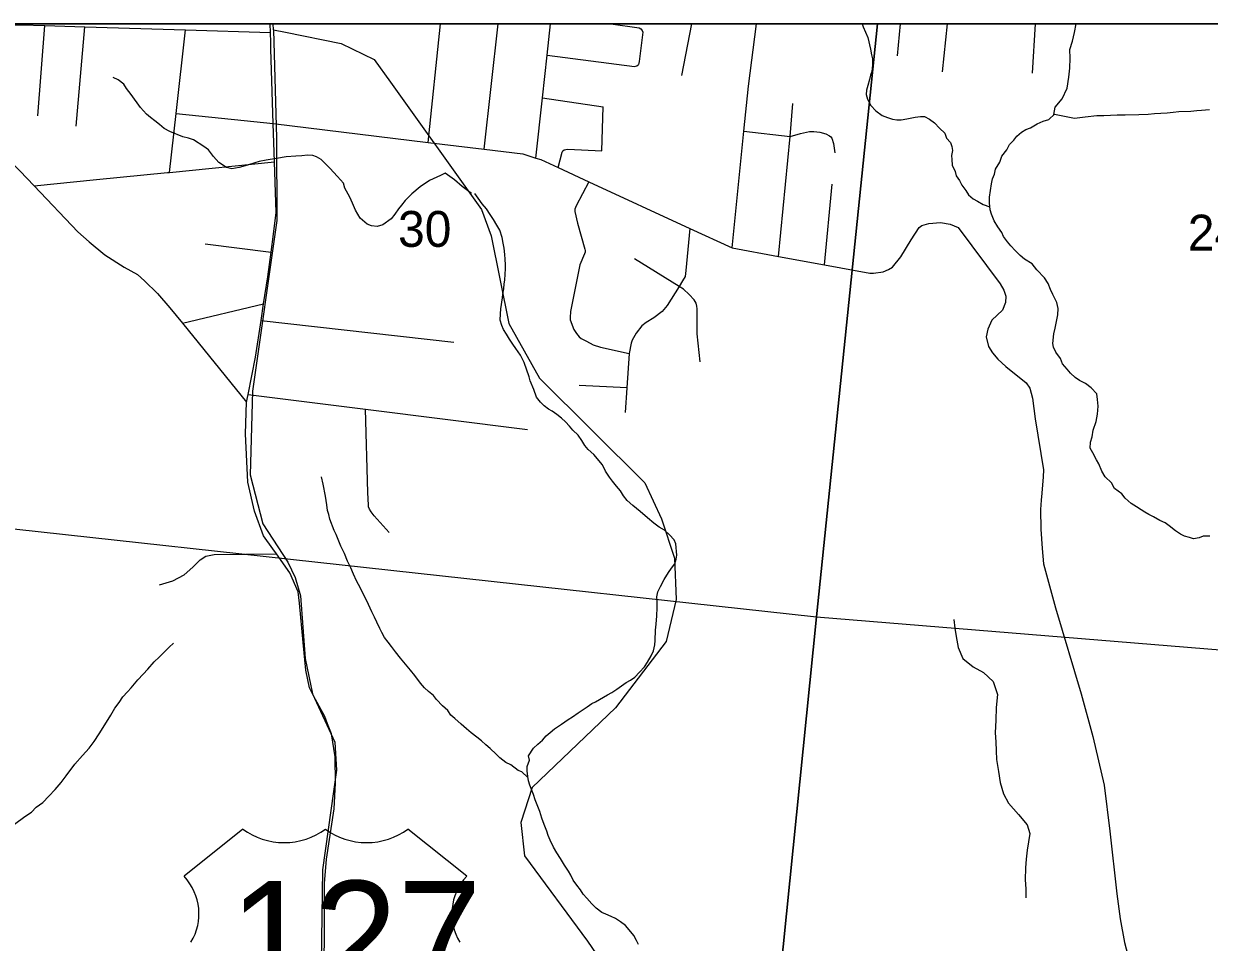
# Model space of a CAD drawing. Extents: x -8.2 to 38.5, y -0.1 to 21.9.
# Drawn here: x 5.115 to 6.498, y 19.692 to 20.764 of the extents above; entities that cross this region are included whole.
import ezdxf

# ---------------------------------------------------------------- set-up
doc = ezdxf.new("R2010")
doc.units = 0
for name, color, linetype in [('Default', 7, 'Continuous'), ('GM_X_Adjacent_County_Text', 7, 'Continuous'), ('GM_X_Airport_Location_Class_3', 7, 'Continuous'), ('GM_X_County_Road_Text', 7, 'Continuous'), ('GM_X_Minor_River', 7, 'Continuous'), ('GM_X_Section', 7, 'Continuous'), ('GM_X_Township', 7, 'Continuous'), ('GM_X_Township_Road_Text', 7, 'Continuous'), ('GM_X_Township_Subdivision', 7, 'Continuous'), ('GM_X_Township_Subdivision_Text', 7, 'Continuous'), ('GM_X_Township_Text', 7, 'Continuous'), ('GM_X_US_Location', 7, 'Continuous')]:
    doc.layers.add(name, color=color, linetype=linetype)

msp = doc.modelspace()

# ---------------------------------------------------------------- linework, layer by layer
at = {"layer": 'Default'}
msp.add_lwpolyline([(8.9634, 15.3136), (8.9634, 20.7535), (8.8842, 20.7645), (4.0666, 20.7645), (4.0665, 20.7635), (4.0467, 20.5533), (4.0404, 20.4649), (4.0302, 20.3597), (3.9961, 19.9817), (3.9436, 19.3979), (3.9289, 19.2353), (3.8854, 18.7517), (3.8472, 18.3279), (3.8449, 18.303), (3.8435, 18.2895), (3.8184, 18.0516), (3.7486, 17.3899)], dxfattribs=at)
for points in [[(6.1116, 20.7645), (5.1033, 20.7645), (5.0467, 20.1811), (6.0401, 20.072)], [(7.1182, 20.7645), (6.1116, 20.7645), (6.0401, 20.072), (7.0485, 19.9899)]]:
    msp.add_lwpolyline(points, close=True, dxfattribs=at)
at = {"layer": 'GM_X_Adjacent_County_Text'}
for points in [[(5.0467, 20.1811), (6.0401, 20.072), (5.9396, 19.0747), (4.9457, 19.1792)], [(7.0485, 19.9899), (6.9585, 18.9896), (5.9396, 19.0747), (6.0401, 20.072)]]:
    msp.add_lwpolyline(points, close=True, dxfattribs=at)
at = {"layer": 'GM_X_Airport_Location_Class_3'}
for points in [[(5.4039, 20.7347), (5.4037, 20.7424), (5.4032, 20.7543), (5.4029, 20.7645)], [(5.3755, 20.3227), (5.3773, 20.3318), (5.3857, 20.3754), (5.3923, 20.4181), (5.3953, 20.4374), (5.4002, 20.469), (5.4041, 20.4979), (5.4069, 20.5189), (5.4098, 20.5442), (5.4087, 20.5796), (5.4079, 20.6031), (5.4066, 20.6479), (5.4039, 20.7347)], [(5.4102, 20.1456), (5.406, 20.1515), (5.3952, 20.1668), (5.3846, 20.1954), (5.3769, 20.2295), (5.374, 20.2859), (5.3755, 20.3227)], [(5.4414, 20.0422), (5.437, 20.0883), (5.4357, 20.1013), (5.426, 20.1234), (5.4102, 20.1456)], [(5.47, 19.9472), (5.4668, 19.956), (5.4534, 19.9801), (5.4488, 19.9894), (5.4444, 20.0101), (5.4414, 20.0422)], [(5.466, 19.6771), (5.4665, 19.6943), (5.4664, 19.7372), (5.4662, 19.7608), (5.4686, 19.7892), (5.4775, 19.8481), (5.4791, 19.878), (5.4789, 19.9088), (5.4743, 19.9356), (5.47, 19.9472)]]:
    msp.add_lwpolyline(points, dxfattribs=at)
at = {"layer": 'GM_X_Minor_River'}
for points in [[(6.0934, 20.7645), (6.0947, 20.7608), (6.0976, 20.7546), (6.1001, 20.7484), (6.1031, 20.7346), (6.1045, 20.7281), (6.1055, 20.7235), (6.1057, 20.7163), (6.1047, 20.7087), (6.1034, 20.7042), (6.1022, 20.6993), (6.1001, 20.6925), (6.0984, 20.6868), (6.0983, 20.6819), (6.0997, 20.6765), (6.1036, 20.6688), (6.1096, 20.6629), (6.117, 20.6573), (6.123, 20.6549), (6.1291, 20.6532), (6.134, 20.6523), (6.1389, 20.6522), (6.1458, 20.6535), (6.1554, 20.6555), (6.1615, 20.6561), (6.1664, 20.656), (6.172, 20.6531), (6.178, 20.6488), (6.1839, 20.6425), (6.1899, 20.6367), (6.192, 20.6309), (6.1964, 20.6258), (6.1982, 20.6212), (6.1988, 20.6166), (6.1979, 20.6105), (6.1982, 20.606), (6.1987, 20.5995), (6.202, 20.5918), (6.2033, 20.5868), (6.207, 20.5814), (6.2099, 20.576), (6.2143, 20.5697), (6.2176, 20.5647), (6.2232, 20.56), (6.228, 20.5572), (6.2348, 20.5536), (6.2425, 20.5509)], [(6.317, 20.6583), (6.3187, 20.6669), (6.3269, 20.6766), (6.3325, 20.6894), (6.3347, 20.7019), (6.3357, 20.7125), (6.336, 20.7243), (6.3359, 20.7342), (6.3388, 20.744), (6.3413, 20.7542), (6.3432, 20.7645)], [(5.6377, 20.5661), (5.6269, 20.5744), (5.618, 20.5822), (5.6072, 20.5901), (5.6018, 20.5873), (5.5887, 20.5815), (5.5778, 20.5742), (5.5681, 20.5657), (5.5603, 20.558), (5.5563, 20.5527), (5.5528, 20.5483), (5.5484, 20.5423), (5.5441, 20.5367), (5.5344, 20.5298), (5.5279, 20.5277), (5.5211, 20.5286), (5.5162, 20.5306), (5.508, 20.5373), (5.5026, 20.547), (5.499, 20.5551), (5.4957, 20.562), (5.4899, 20.5725), (5.4886, 20.5782), (5.4816, 20.586), (5.4727, 20.5958), (5.4671, 20.6013), (5.4623, 20.606), (5.4571, 20.6092), (5.4526, 20.6108), (5.4465, 20.611), (5.44, 20.6101), (5.4328, 20.6099), (5.4217, 20.609), (5.4103, 20.6071), (5.3984, 20.6051), (5.39, 20.6035), (5.385, 20.6021), (5.3766, 20.5993), (5.3666, 20.5965), (5.3582, 20.5952), (5.3518, 20.5965), (5.3432, 20.6025), (5.3369, 20.6095), (5.331, 20.6173), (5.3254, 20.6212), (5.3135, 20.6288), (5.3075, 20.6309), (5.301, 20.6326), (5.286, 20.6387), (5.2792, 20.6423), (5.2737, 20.6467), (5.2684, 20.651), (5.2632, 20.655), (5.2588, 20.6589), (5.2518, 20.6667), (5.2408, 20.6819), (5.2352, 20.6889), (5.2323, 20.6939), (5.2256, 20.699), (5.2196, 20.7015)], [(6.4232, 20.1943), (6.4188, 20.1971), (6.4135, 20.2007), (6.4075, 20.2046), (6.4005, 20.2105), (6.3964, 20.2156), (6.3879, 20.2219), (6.3842, 20.2285), (6.3768, 20.2356), (6.3732, 20.2421), (6.3696, 20.2506), (6.3667, 20.2553), (6.3627, 20.2637), (6.3595, 20.2692), (6.36, 20.276), (6.3617, 20.2824), (6.3631, 20.29), (6.3664, 20.3002), (6.3681, 20.3089), (6.3688, 20.318), (6.3682, 20.326), (6.3672, 20.3325), (6.3606, 20.3395), (6.3539, 20.3447), (6.3471, 20.3479), (6.3419, 20.3515), (6.3367, 20.3566), (6.3327, 20.3613), (6.3271, 20.3675), (6.325, 20.3737), (6.3195, 20.381), (6.3166, 20.3868), (6.316, 20.3914), (6.317, 20.4024), (6.3187, 20.4092), (6.32, 20.4149), (6.3218, 20.4247), (6.322, 20.432), (6.3207, 20.4392), (6.316, 20.4485), (6.3131, 20.4543), (6.3106, 20.4612), (6.3062, 20.4678), (6.2974, 20.4772), (6.2918, 20.4842), (6.2829, 20.4898), (6.2777, 20.4941), (6.2721, 20.4996), (6.2669, 20.5051), (6.2629, 20.5098), (6.2585, 20.516), (6.2563, 20.5206), (6.2519, 20.5272), (6.2476, 20.5345), (6.2444, 20.5422), (6.243, 20.5472), (6.242, 20.5553), (6.2422, 20.5621), (6.2432, 20.5697), (6.2445, 20.5776), (6.2455, 20.5833), (6.2479, 20.589), (6.2492, 20.5946), (6.254, 20.6029), (6.2564, 20.61), (6.2623, 20.6171), (6.2652, 20.6235), (6.2703, 20.6287), (6.2738, 20.6332), (6.2793, 20.638), (6.2843, 20.6409), (6.29, 20.643), (6.2978, 20.6477), (6.3047, 20.6506), (6.3112, 20.6527), (6.3177, 20.659), (6.3413, 20.6541), (6.3535, 20.6557), (6.3672, 20.6572), (6.3756, 20.6573), (6.3908, 20.6581), (6.4003, 20.6582), (6.4163, 20.6585), (6.427, 20.6589), (6.4346, 20.6595), (6.4495, 20.6606), (6.4563, 20.6612), (6.4628, 20.6618), (6.4769, 20.6625), (6.4841, 20.6631), (6.4895, 20.6637), (6.4986, 20.6642)], [(5.8472, 20.0265), (5.85, 20.0326), (5.8517, 20.0397), (5.8522, 20.0447), (5.8525, 20.0565), (5.8531, 20.0637), (5.8541, 20.0732), (5.8544, 20.0827), (5.8542, 20.0907), (5.854, 20.0956), (5.8553, 20.1013), (5.8581, 20.1077), (5.8625, 20.1159), (5.8677, 20.1238), (5.8712, 20.129), (5.8748, 20.1339), (5.8764, 20.1395), (5.8773, 20.1441), (5.8762, 20.1574), (5.8744, 20.1621), (5.8688, 20.1679), (5.8629, 20.1734), (5.8569, 20.177), (5.8506, 20.1817), (5.8431, 20.1877), (5.8346, 20.1951), (5.826, 20.2022), (5.8193, 20.2081), (5.8153, 20.2136), (5.8117, 20.2194), (5.8069, 20.2248), (5.8021, 20.2307), (5.7988, 20.2353), (5.794, 20.2423), (5.7908, 20.2497), (5.7805, 20.2617), (5.7738, 20.2676), (5.7701, 20.2723), (5.7665, 20.2781), (5.7621, 20.2843), (5.7561, 20.2902), (5.7521, 20.2949), (5.7476, 20.2996), (5.7428, 20.3039), (5.7372, 20.3082), (5.732, 20.3122), (5.7275, 20.3146), (5.7227, 20.3186), (5.7182, 20.3229), (5.7138, 20.3287), (5.7106, 20.3375), (5.7063, 20.3476), (5.7049, 20.3522), (5.6993, 20.3691), (5.695, 20.3776), (5.6895, 20.3853), (5.6862, 20.3904), (5.6822, 20.3962), (5.6785, 20.402), (5.6753, 20.4074), (5.6731, 20.4124), (5.6714, 20.4186), (5.6716, 20.4258), (5.6721, 20.4315), (5.674, 20.4444), (5.6745, 20.4489), (5.6754, 20.455), (5.6759, 20.4607), (5.6768, 20.4652), (5.677, 20.4721), (5.6775, 20.4782), (5.6773, 20.4831), (5.6771, 20.4896), (5.6768, 20.4949), (5.6759, 20.5026), (5.6749, 20.5083), (5.6736, 20.5148), (5.6708, 20.5233), (5.6675, 20.5295), (5.6635, 20.536), (5.6595, 20.5419), (5.6551, 20.5485), (5.6503, 20.5543), (5.6455, 20.5609), (5.6415, 20.5663)], [(5.7037, 19.8846), (5.6967, 19.8914), (5.6922, 19.8927), (5.6836, 19.8994), (5.678, 19.9022), (5.6709, 19.9078), (5.6665, 19.9121), (5.6594, 19.9184), (5.6546, 19.9227), (5.6494, 19.9274), (5.6442, 19.9317), (5.6375, 19.9369), (5.6319, 19.9416), (5.6256, 19.9471), (5.6182, 19.9534), (5.6137, 19.9573), (5.6101, 19.9627), (5.6041, 19.9682), (5.5971, 19.9757), (5.5934, 19.9803), (5.5878, 19.9851), (5.583, 19.9894), (5.5782, 19.9948), (5.5716, 20.0038), (5.5665, 20.01), (5.5609, 20.017), (5.555, 20.024), (5.5492, 20.0314), (5.5444, 20.0377), (5.5407, 20.0427), (5.5363, 20.0482), (5.533, 20.054), (5.5309, 20.0586), (5.5273, 20.0659), (5.5248, 20.0717), (5.5215, 20.0779), (5.5175, 20.0864), (5.5082, 20.1057), (5.5038, 20.1142), (5.5003, 20.1219), (5.497, 20.1292), (5.4931, 20.1373), (5.4895, 20.1462), (5.4855, 20.1546), (5.4823, 20.1623), (5.4798, 20.1681), (5.4777, 20.1728), (5.4727, 20.1862), (5.4713, 20.1916), (5.4699, 20.1962), (5.469, 20.2031), (5.4673, 20.213), (5.4647, 20.2272), (5.463, 20.2356)], [(6.4989, 20.1663), (6.4913, 20.1665), (6.4867, 20.1644), (6.4802, 20.1634), (6.4753, 20.1647), (6.4696, 20.1664), (6.4648, 20.1688), (6.4592, 20.1727), (6.4517, 20.1783), (6.4469, 20.1818), (6.4409, 20.1847), (6.4334, 20.1891), (6.4281, 20.1915), (6.4232, 20.1943)], [(6.2005, 20.0692), (6.2018, 20.0589), (6.2031, 20.0493), (6.2054, 20.0363), (6.2108, 20.0237), (6.2231, 20.0139), (6.2351, 20.0071), (6.2463, 19.9966), (6.2512, 19.9816), (6.2497, 19.9665), (6.2494, 19.9516), (6.2486, 19.9368), (6.2495, 19.9262), (6.25, 19.9159), (6.2502, 19.9056), (6.2525, 19.8915), (6.2545, 19.8789), (6.2583, 19.8655), (6.2641, 19.8547), (6.276, 19.8415), (6.286, 19.8295), (6.2891, 19.8195), (6.2874, 19.8097), (6.286, 19.7998), (6.285, 19.7892), (6.284, 19.7793), (6.2836, 19.7653), (6.2845, 19.7546), (6.2843, 19.7444)], [(5.1045, 19.8303), (5.1169, 19.8391), (5.1247, 19.8442), (5.1301, 19.8501), (5.1379, 19.8556), (5.1449, 19.863), (5.152, 19.8708), (5.1591, 19.879), (5.165, 19.8868), (5.1749, 19.9003), (5.1842, 19.9103), (5.1917, 19.9188), (5.1976, 19.9267), (5.2036, 19.9356), (5.2099, 19.9461), (5.2171, 19.9573), (5.2219, 19.9656), (5.2266, 19.9723), (5.231, 19.9787), (5.2364, 19.9846), (5.2408, 19.9894), (5.2486, 19.9987), (5.2549, 20.0054), (5.2604, 20.0113), (5.2678, 20.0195), (5.2733, 20.0251), (5.2784, 20.0302), (5.285, 20.0369), (5.2901, 20.0413)], [(5.8328, 19.6897), (5.8302, 19.6943), (5.827, 19.7001), (5.8218, 19.7067), (5.8174, 19.7118), (5.8118, 19.7162), (5.8058, 19.7201), (5.8006, 19.7226), (5.7946, 19.725), (5.7897, 19.727), (5.7834, 19.7322), (5.7782, 19.7373), (5.7723, 19.7439), (5.7682, 19.7486), (5.7649, 19.7536), (5.7605, 19.7591), (5.7565, 19.7649), (5.7536, 19.7707), (5.751, 19.7753), (5.7463, 19.7823), (5.7416, 19.7901), (5.7372, 19.7967), (5.7335, 19.8032), (5.7296, 19.8117), (5.7274, 19.8171), (5.7257, 19.8221), (5.7225, 19.8298), (5.72, 19.8371), (5.7175, 19.8448), (5.7143, 19.8529), (5.7122, 19.8586), (5.7101, 19.8648), (5.7058, 19.8756), (5.7044, 19.8806), (5.7034, 19.8859), (5.7029, 19.8924), (5.7026, 19.8977), (5.7055, 19.9049), (5.7041, 19.9099), (5.71, 19.9188), (5.7151, 19.9236), (5.7206, 19.9284), (5.7249, 19.9333), (5.7295, 19.937), (5.7346, 19.9414), (5.7427, 19.9469), (5.7505, 19.9524), (5.7555, 19.9556), (5.7621, 19.96), (5.7679, 19.964), (5.7726, 19.9673), (5.778, 19.971), (5.7826, 19.9728), (5.7919, 19.9786), (5.7965, 19.9811), (5.8015, 19.984), (5.8073, 19.9877), (5.8182, 19.9954), (5.8232, 19.9983), (5.8282, 20.0016), (5.8337, 20.0075), (5.8396, 20.0138), (5.8432, 20.0194), (5.8472, 20.0265)]]:
    msp.add_lwpolyline(points, dxfattribs=at)
at = {"layer": 'GM_X_Section'}
msp.add_lwpolyline([(8.9634, 15.3136), (8.9634, 20.7645), (2.1634, 20.7645), (2.1634, 13.9645)], dxfattribs=at)
at = {"layer": 'GM_X_Township'}
msp.add_line((2.1634, 20.7645), (8.9634, 20.7645), dxfattribs=at)
at = {"layer": 'GM_X_Township_Subdivision'}
for p, q in [((5.3712, 19.8244), (5.3026, 19.7695)), ((5.6322, 19.7695), (5.5635, 19.8244))]:
    msp.add_line(p, q, dxfattribs=at)
for centre, major_axis, start_param, end_param in [((5.4193, 19.8637), (-0.0687, 0), 0.795399, 2.346194), ((5.5154, 19.8637), (-0.0687, 0), 0.795399, 2.346194), ((5.2238, 19.7254), (0.0961, 0), 5.838949, 6.894067), ((5.7109, 19.7254), (-0.0961, 0), 5.672304, 6.727422)]:
    msp.add_ellipse(centre, major_axis=major_axis, ratio=0.8, start_param=start_param, end_param=end_param, dxfattribs=at)
at = {"layer": 'GM_X_Township_Subdivision_Text'}
for p, q in [((5.132, 20.657), (5.1402, 20.7622)), ((5.1766, 20.6447), (5.1869, 20.7608)), ((5.5873, 20.6259), (5.6018, 20.7645)), ((5.6527, 20.6179), (5.6688, 20.7645)), ((5.883, 20.7039), (5.8948, 20.7645)), ((6.1349, 20.7269), (6.1384, 20.7645)), ((6.1925, 20.7645), (6.187, 20.7083)), ((6.2952, 20.7645), (6.2918, 20.7066)), ((5.7206, 20.6778), (5.7915, 20.6675)), ((5.79, 20.6162), (5.7915, 20.6675)), ((6.0494, 20.483), (6.0586, 20.5773)), ((5.3273, 20.5075), (5.4041, 20.4979)), ((5.3005, 20.4149), (5.3953, 20.4374)), ((5.3923, 20.4181), (5.6172, 20.3926)), ((5.819, 20.3394), (5.7633, 20.3422))]:
    msp.add_line(p, q, dxfattribs=at)
for points in [[(5.7129, 20.6075), (5.7206, 20.6778), (5.7261, 20.7278), (5.7301, 20.7645)], [(5.8005, 20.7645), (5.8334, 20.7597), (5.8353, 20.7585), (5.8369, 20.7566), (5.8378, 20.7546), (5.8333, 20.7202), (5.8325, 20.7168)], [(5.2856, 20.5909), (5.2933, 20.6598), (5.3042, 20.7573)], [(5.7261, 20.7278), (5.8279, 20.7147), (5.8306, 20.7154), (5.8325, 20.7168)], [(5.9959, 20.4928), (6.0096, 20.633), (6.0126, 20.6712)], [(5.2933, 20.6598), (5.3726, 20.6514), (5.4066, 20.6479)], [(5.9556, 20.6391), (6.0096, 20.633), (6.0214, 20.6365), (6.0321, 20.6386), (6.0373, 20.6388), (6.0443, 20.6379), (6.0511, 20.6359), (6.0555, 20.6335), (6.0569, 20.6323), (6.0582, 20.6308), (6.0599, 20.6247), (6.0616, 20.6137)], [(5.7388, 20.5965), (5.7436, 20.6145), (5.7445, 20.6159), (5.7459, 20.6171), (5.748, 20.6178), (5.7502, 20.6182), (5.79, 20.6162)], [(5.1276, 20.5753), (5.2002, 20.5825), (5.2833, 20.5907), (5.2856, 20.5909), (5.4079, 20.6031)], [(5.7745, 20.58), (5.7599, 20.5519), (5.7585, 20.5481), (5.7582, 20.5454), (5.7613, 20.5317), (5.7699, 20.5015), (5.7702, 20.4997), (5.7702, 20.4979), (5.7697, 20.4958), (5.7642, 20.483), (5.7532, 20.4286), (5.7527, 20.4216), (5.753, 20.4187), (5.7573, 20.4076), (5.7602, 20.4027), (5.7633, 20.3991), (5.7659, 20.397), (5.7719, 20.394), (5.7798, 20.3897), (5.7881, 20.3868), (5.8218, 20.3797)], [(5.8923, 20.5256), (5.8879, 20.4763), (5.887, 20.4695), (5.8839, 20.4643), (5.88, 20.4579), (5.8662, 20.4354), (5.8604, 20.4287), (5.8503, 20.4213), (5.8417, 20.4159), (5.8365, 20.4117), (5.83, 20.4032), (5.8251, 20.3952), (5.8241, 20.3916), (5.8218, 20.3797), (5.819, 20.3394), (5.817, 20.3107)], [(5.9044, 20.37), (5.9009, 20.4024), (5.9011, 20.4317), (5.9007, 20.4347), (5.8997, 20.4382), (5.8975, 20.4423), (5.8919, 20.4485), (5.8852, 20.4547), (5.88, 20.4579), (5.8278, 20.4901)], [(5.3773, 20.3318), (5.5143, 20.3146), (5.703, 20.291)], [(5.5417, 20.1705), (5.5243, 20.1902), (5.5206, 20.1948), (5.5188, 20.1977), (5.5176, 20.2006), (5.5175, 20.2024), (5.5168, 20.2173), (5.5143, 20.3146)], [(5.2738, 20.1095), (5.2895, 20.1141), (5.3025, 20.1214), (5.3126, 20.1303), (5.3211, 20.1389), (5.3277, 20.1429), (5.3376, 20.145), (5.4102, 20.1456)]]:
    msp.add_lwpolyline(points, dxfattribs=at)
at = {"layer": 'GM_X_Township_Text'}
for points in [[(5.0045, 20.7645), (5.0174, 20.7317), (5.0267, 20.7089), (5.0371, 20.6867), (5.0517, 20.6653), (5.0659, 20.6447), (5.0876, 20.6152), (5.1109, 20.5929), (5.1276, 20.5753), (5.1784, 20.5216), (5.1916, 20.51), (5.21, 20.4946), (5.2326, 20.4804), (5.2481, 20.4718), (5.2564, 20.4645), (5.2714, 20.4496), (5.286, 20.4327), (5.3005, 20.4149), (5.3755, 20.3227)], [(5.0565, 20.7645), (5.0788, 20.763), (5.0904, 20.763), (5.1134, 20.763), (5.1402, 20.7622), (5.1869, 20.7608), (5.3042, 20.7573), (5.4032, 20.7543)], [(5.9419, 20.5028), (5.9556, 20.6391), (5.9609, 20.6916), (5.9702, 20.7645)], [(5.4066, 20.6479), (5.5873, 20.6259), (5.6527, 20.6179), (5.6975, 20.6124), (5.707, 20.6093), (5.7129, 20.6075), (5.7187, 20.6058), (5.7388, 20.5965), (5.7745, 20.58), (5.8923, 20.5256), (5.9419, 20.5028), (5.9959, 20.4928), (6.0494, 20.483), (6.1024, 20.4733), (6.1069, 20.4733), (6.118, 20.475), (6.1243, 20.4774), (6.129, 20.4802), (6.1387, 20.4923), (6.1506, 20.5123), (6.1599, 20.5266), (6.1633, 20.5291), (6.1713, 20.5314), (6.185, 20.5324), (6.1963, 20.5304), (6.2054, 20.5265), (6.2544, 20.4607), (6.2589, 20.4534), (6.2611, 20.4466), (6.2606, 20.439), (6.2571, 20.4303), (6.2449, 20.4183), (6.2402, 20.4081), (6.2382, 20.399), (6.2408, 20.3879), (6.2456, 20.3803), (6.2516, 20.373), (6.261, 20.3645), (6.2847, 20.3453), (6.2892, 20.3392), (6.2921, 20.3274), (6.2953, 20.3031), (6.3049, 20.2437), (6.3045, 20.2354), (6.303, 20.2164), (6.3023, 20.2084)], [(6.3023, 20.2084), (6.3014, 20.1975), (6.302, 20.1747), (6.3036, 20.1519), (6.305, 20.134), (6.3189, 20.0826), (6.349, 19.9824), (6.3625, 19.9326), (6.376, 19.8759), (6.3826, 19.8222), (6.3906, 19.7489), (6.3945, 19.7196), (6.3995, 19.6922), (6.4258, 19.5921), (6.4312, 19.5594), (6.436, 19.5464), (6.4427, 19.5346), (6.4528, 19.5227), (6.489, 19.4976), (6.7912, 19.2826)]]:
    msp.add_lwpolyline(points, dxfattribs=at)
at = {"layer": 'GM_X_US_Location'}
msp.add_line((5.4067, 20.7573), (5.4065, 20.7645), dxfattribs=at)
for points in [[(5.4067, 20.7573), (5.4105, 20.631), (5.4106, 20.5348), (5.3824, 20.3355), (5.3797, 20.2378), (5.3942, 20.1806), (5.4234, 20.136), (5.432, 20.1182), (5.4382, 20.0967), (5.4439, 20.0235), (5.4522, 19.9822), (5.4783, 19.9259), (5.4804, 19.8933), (5.4639, 19.777), (5.4623, 19.6693)], [(5.4067, 20.7573), (5.4207, 20.7545), (5.4858, 20.7414), (5.5242, 20.7225), (5.5433, 20.6962), (5.6493, 20.5476), (5.6608, 20.517), (5.6813, 20.4145), (5.717, 20.3506), (5.8398, 20.2285), (5.8596, 20.1864), (5.8747, 20.1405), (5.8765, 20.0923), (5.8649, 20.0435), (5.8056, 19.966), (5.7084, 19.8731), (5.6955, 19.832), (5.6998, 19.7932), (5.7733, 19.6938), (5.81, 19.6397)]]:
    msp.add_lwpolyline(points, dxfattribs=at)

# ---------------------------------------------------------------- texts
at = {"layer": 'GM_X_County_Road_Text'}
for s, p in [('30', (5.5521, 20.504)), ('24', (6.4734, 20.4997))]:
    msp.add_text(s, height=0.04186, rotation=0, dxfattribs=at).set_placement(p)
at = {"layer": 'GM_X_Township_Road_Text'}
for s in ['0', '/']:
    msp.add_text(s, height=0.000189, dxfattribs=at).set_placement((5.4675, 19.698))
at = {"layer": 'GM_X_Township_Subdivision'}
msp.add_text('127', height=0.13184, dxfattribs=at).set_placement((5.3555, 19.6322))

doc.saveas('drawing.dxf')
